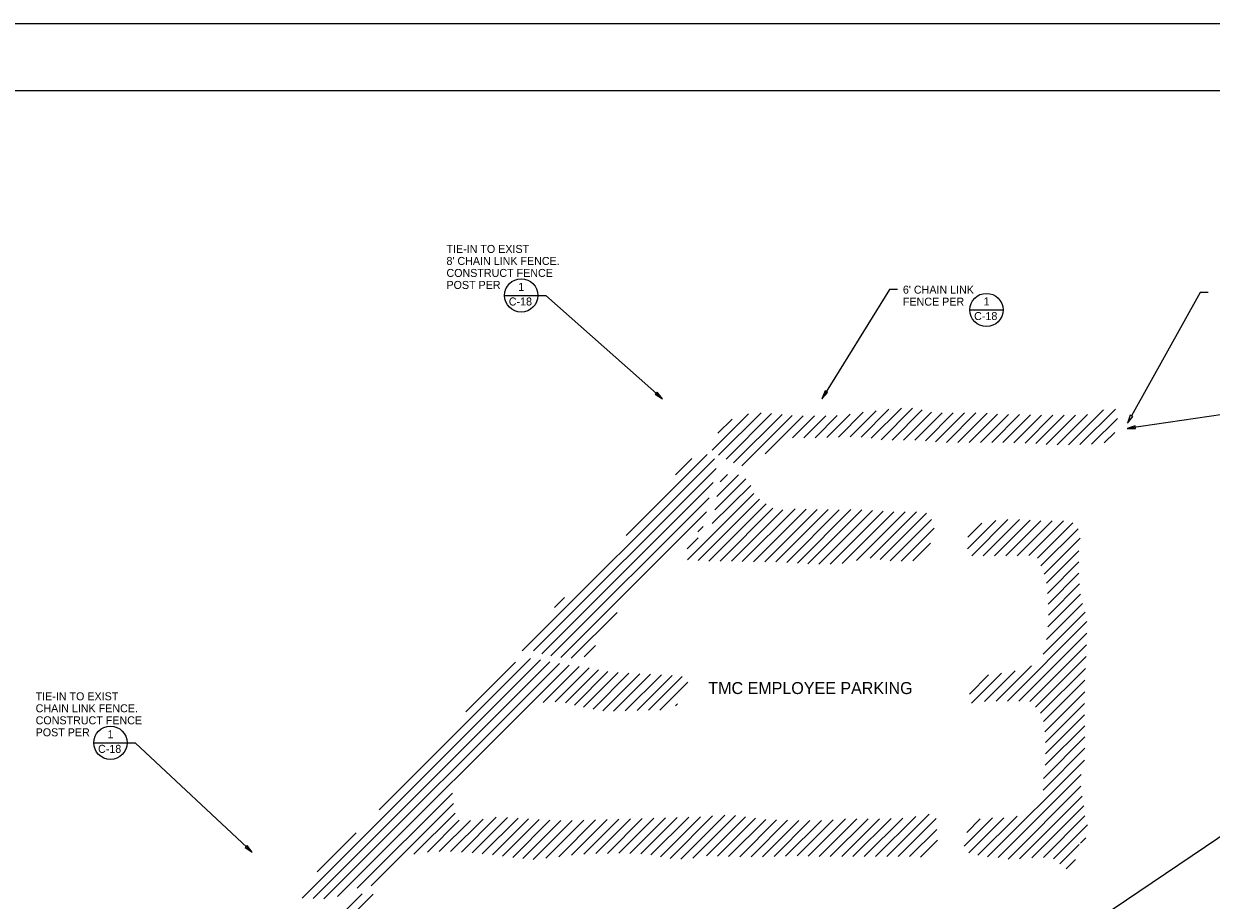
# Model space of a CAD drawing. Extents: x 0 to 3.5, y 0 to 2.5.
# Drawn here: x 0.765 to 2.248, y 1.404 to 2.5 of the extents above; entities that cross this region are included whole.
import ezdxf

# ---------------------------------------------------------------- set-up
doc = ezdxf.new("R2010")
doc.units = 0
for name, color, linetype in [('C-MARK', 7, 'Continuous'), ('C-TEXT', 7, 'Continuous'), ('C-TEXT-TITL', 7, 'Continuous'), ('G-TTLB-OTLN', 7, 'Continuous'), ('G-TTLB-VIEW', 7, 'Continuous'), ('Pavement Hatch', 7, 'Continuous')]:
    doc.layers.add(name, color=color, linetype=linetype)

msp = doc.modelspace()

# ---------------------------------------------------------------- linework, layer by layer
at = {"layer": 'C-MARK'}
for p, q in [((1.3652, 2.1604), (1.4069, 2.1604)), ((1.9466, 2.1422), (1.9882, 2.1422)), ((0.852, 1.6012), (0.8936, 1.6012))]:
    msp.add_line(p, q, dxfattribs=at)
for points in [[(1.8564, 2.1678), (1.8464, 2.1678), (1.7619, 2.0313)], [(1.4069, 2.1604), (1.4169, 2.1604), (1.5626, 2.0313)], [(2.2446, 2.164), (2.2346, 2.164), (2.1487, 2.01)], [(2.29, 2.0142), (2.28, 2.0142), (2.1431, 1.9941)], [(0.8936, 1.6012), (0.9036, 1.6012), (1.0499, 1.4646)], [(2.3985, 1.5709), (2.3885, 1.5709), (2.1092, 1.3821)]]:
    msp.add_lwpolyline(points, dxfattribs=at)
for centre in [(1.3861, 2.1604), (1.9674, 2.1422), (0.8728, 1.6012)]:
    msp.add_circle(centre, 0.0208, dxfattribs=at)
at = {"layer": 'C-TEXT'}
for points in [[(1.5536, 2.0368), (1.5626, 2.0313), (1.556, 2.0395)], [(1.7658, 2.0411), (1.7619, 2.0313), (1.7689, 2.0392)], [(2.1471, 2.0109), (2.1436, 2.0009), (2.1503, 2.0091)], [(2.1531, 1.9975), (2.1431, 1.9941), (2.1536, 1.9939)], [(1.041, 1.4703), (1.0499, 1.4646), (1.0435, 1.473)]]:
    msp.add_lwpolyline(points, close=True, dxfattribs=at)
at = {"layer": 'G-TTLB-OTLN'}
msp.add_lwpolyline([(0, 0), (3.5, 0), (3.5, 2.5), (0, 2.5)], close=True, dxfattribs=at)
at = {"layer": 'G-TTLB-VIEW'}
msp.add_lwpolyline([(0.1667, 2.4167), (3.0729, 2.4167), (3.0729, 0.0833), (0.1667, 0.0833)], close=True, dxfattribs=at)
at = {"layer": 'Pavement Hatch'}
for p, q in [((1.8108, 1.9833), (1.8456, 2.0181)), ((1.8234, 1.9818), (1.8612, 2.0195)), ((1.8357, 1.9799), (1.8751, 2.0193)), ((2.0842, 1.9739), (2.1286, 2.0182)), ((1.6247, 1.9668), (1.6702, 2.0124)), ((1.6317, 1.9881), (1.6495, 2.0058)), ((1.6326, 1.9607), (1.6857, 2.0138)), ((1.642, 1.9559), (1.6987, 2.0126)), ((1.6513, 1.9511), (1.712, 2.0117)), ((1.6617, 1.9473), (1.7248, 2.0105)), ((1.691, 1.9625), (1.7384, 2.0098)), ((1.7249, 1.9822), (1.7525, 2.0098)), ((1.7391, 1.9823), (1.7665, 2.0097)), ((1.7533, 1.9824), (1.781, 2.0101)), ((1.768, 1.9829), (1.7971, 2.012)), ((1.7826, 1.9834), (1.8135, 2.0143)), ((1.7969, 1.9835), (1.8296, 2.0163)), ((1.8495, 1.9795), (1.8871, 2.0172)), ((1.8636, 1.9795), (1.8987, 2.0146)), ((1.8777, 1.9795), (1.9119, 2.0136)), ((1.8911, 1.9788), (1.926, 2.0136)), ((1.9037, 1.9772), (1.9401, 2.0136)), ((1.9173, 1.9767), (1.9543, 2.0136)), ((1.9315, 1.9767), (1.9682, 2.0134)), ((1.9456, 1.9767), (1.981, 2.012)), ((1.9598, 1.9767), (1.9948, 2.0117)), ((1.9739, 1.9767), (2.0086, 2.0114)), ((1.9879, 1.9765), (2.0224, 2.011)), ((2.0018, 1.9763), (2.0363, 2.0108)), ((2.0156, 1.9759), (2.0504, 2.0108)), ((2.0291, 1.9753), (2.0646, 2.0108)), ((2.0419, 1.974), (2.0787, 2.0108)), ((2.0559, 1.9738), (2.0936, 2.0115)), ((2.07, 1.9738), (2.1136, 2.0174)), ((2.0988, 1.9743), (2.1312, 2.0067)), ((2.1146, 1.976), (2.1277, 1.989)), ((1.5173, 1.8603), (1.6185, 1.9615)), ((1.691, 1.9625), (1.691, 1.9625)), ((1.3873, 1.7161), (1.6274, 1.9562)), ((1.4014, 1.7161), (1.6295, 1.9442)), ((1.579, 1.9361), (1.5993, 1.9564)), ((1.6279, 1.8923), (1.6669, 1.9313)), ((1.6304, 1.9089), (1.6574, 1.936)), ((1.6346, 1.9273), (1.6438, 1.9365)), ((1.4119, 1.7124), (1.6259, 1.9264)), ((1.6248, 1.8751), (1.6728, 1.923)), ((1.4233, 1.7097), (1.621, 1.9074)), ((1.5937, 1.8298), (1.6767, 1.9128)), ((1.6071, 1.8291), (1.6837, 1.9057)), ((1.6205, 1.8284), (1.6921, 1.8999)), ((1.4354, 1.7076), (1.6175, 1.8897)), ((1.6347, 1.8284), (1.7006, 1.8943)), ((1.6487, 1.8283), (1.7129, 1.8925)), ((1.6623, 1.8278), (1.7283, 1.8937)), ((1.6762, 1.8274), (1.7421, 1.8934)), ((1.6903, 1.8275), (1.7559, 1.893)), ((1.7044, 1.8274), (1.7697, 1.8927)), ((1.7179, 1.8267), (1.7835, 1.8924)), ((1.7311, 1.8258), (1.798, 1.8928)), ((1.7444, 1.825), (1.8117, 1.8923)), ((1.7579, 1.8244), (1.825, 1.8915)), ((1.772, 1.8243), (1.8384, 1.8906)), ((1.787, 1.8252), (1.8518, 1.89)), ((1.8052, 1.8292), (1.8659, 1.8899)), ((1.822, 1.8318), (1.8801, 1.89)), ((1.8347, 1.8304), (1.8925, 1.8883)), ((1.6068, 1.8649), (1.6133, 1.8714)), ((1.847, 1.8285), (1.8989, 1.8805)), ((1.9435, 1.8435), (1.9789, 1.8789)), ((1.9443, 1.8584), (1.9616, 1.8757)), ((1.9492, 1.835), (1.9943, 1.8801)), ((1.9633, 1.835), (2.0087, 1.8804)), ((1.9775, 1.835), (2.022, 1.8795)), ((1.9916, 1.835), (2.0353, 1.8787)), ((2.0058, 1.835), (2.0494, 1.8786)), ((2.0202, 1.8353), (2.0635, 1.8786)), ((2.031, 1.832), (2.0753, 1.8763)), ((1.5933, 1.8436), (1.607, 1.8573)), ((1.861, 1.8284), (1.9019, 1.8694)), ((2.0355, 1.8223), (2.0818, 1.8687)), ((2.0395, 1.8121), (2.0843, 1.857)), ((1.8755, 1.8288), (1.8973, 1.8506)), ((2.0423, 1.8008), (2.0828, 1.8413)), ((2.0436, 1.788), (2.0828, 1.8272)), ((2.0444, 1.7746), (2.083, 1.8133)), ((2.0448, 1.7609), (2.0835, 1.7997)), ((1.4275, 1.7705), (1.4401, 1.783)), ((2.0441, 1.7461), (2.0848, 1.7868)), ((2.0425, 1.7303), (2.0873, 1.7752)), ((1.4487, 1.7068), (1.506, 1.7641)), ((1.9935, 1.6531), (2.093, 1.7526)), ((2.0383, 1.712), (2.0907, 1.7644)), ((2.0077, 1.6531), (2.093, 1.7384)), ((1.4646, 1.7085), (1.4791, 1.723)), ((2.0217, 1.653), (2.0925, 1.7237)), ((1.2088, 1.5175), (1.3977, 1.7065)), ((2.0288, 1.6459), (2.0919, 1.709)), ((1.1125, 1.4071), (1.4101, 1.7047)), ((1.1261, 1.4065), (1.422, 1.7025)), ((1.1396, 1.406), (1.4339, 1.7002)), ((1.1567, 1.4089), (1.446, 1.6982)), ((1.3169, 1.6398), (1.379, 1.7019)), ((1.4134, 1.6515), (1.4584, 1.6965)), ((1.4284, 1.6523), (1.4708, 1.6947)), ((1.4414, 1.6512), (1.4825, 1.6923)), ((1.9794, 1.6531), (2.0235, 1.6972)), ((2.0351, 1.6381), (2.0912, 1.6942)), ((1.4526, 1.6483), (1.4945, 1.6901)), ((1.4641, 1.6456), (1.5074, 1.6889)), ((1.4758, 1.6431), (1.5207, 1.6881)), ((1.4881, 1.6413), (1.5342, 1.6874)), ((1.5015, 1.6406), (1.5478, 1.6868)), ((1.5161, 1.641), (1.5614, 1.6863)), ((1.5309, 1.6416), (1.5748, 1.6855)), ((1.5451, 1.6418), (1.5873, 1.684)), ((1.5593, 1.6418), (1.5943, 1.6768)), ((1.946, 1.6621), (1.9701, 1.6862)), ((1.9487, 1.6506), (1.9862, 1.6882)), ((1.9649, 1.6528), (2.0033, 1.6911)), ((2.0388, 1.6276), (2.0905, 1.6794)), ((2.0403, 1.615), (2.0901, 1.6648)), ((1.5788, 1.6472), (1.5814, 1.6498)), ((2.0411, 1.6016), (2.0899, 1.6504)), ((2.0411, 1.5875), (2.0899, 1.6363)), ((2.0408, 1.5731), (2.0903, 1.6225)), ((2.0385, 1.5567), (2.0904, 1.6085)), ((2.0381, 1.5421), (2.0904, 1.5943)), ((1.9687, 1.4586), (2.0897, 1.5796)), ((1.9822, 1.4579), (2.0859, 1.5616)), ((1.9944, 1.4559), (2.0854, 1.547)), ((1.1812, 1.4193), (1.3003, 1.5384)), ((2.0086, 1.456), (2.087, 1.5344)), ((1.1985, 1.4224), (1.3014, 1.5253)), ((2.0242, 1.4574), (2.0889, 1.5222)), ((1.252, 1.4618), (1.3034, 1.5132)), ((1.269, 1.4646), (1.3087, 1.5043)), ((1.2837, 1.4652), (1.3226, 1.5041)), ((1.2978, 1.4651), (1.3385, 1.5058)), ((1.3113, 1.4645), (1.3549, 1.5081)), ((1.3247, 1.4637), (1.3688, 1.5078)), ((1.3375, 1.4624), (1.3821, 1.507)), ((1.3502, 1.461), (1.3953, 1.506)), ((1.3629, 1.4595), (1.4084, 1.5051)), ((1.3755, 1.458), (1.4218, 1.5043)), ((1.3882, 1.4566), (1.4357, 1.504)), ((1.4012, 1.4554), (1.4499, 1.5041)), ((1.4167, 1.4568), (1.4643, 1.5043)), ((1.4329, 1.4588), (1.4789, 1.5048)), ((1.4489, 1.4607), (1.4935, 1.5053)), ((1.4642, 1.4619), (1.5082, 1.5058)), ((1.4792, 1.4627), (1.5228, 1.5063)), ((1.4937, 1.463), (1.5372, 1.5066)), ((1.5079, 1.4631), (1.5517, 1.5069)), ((1.5218, 1.4629), (1.5662, 1.5073)), ((1.5356, 1.4625), (1.5808, 1.5077)), ((1.5482, 1.461), (1.5955, 1.5082)), ((1.5601, 1.4588), (1.6102, 1.5088)), ((1.5722, 1.4567), (1.6253, 1.5098)), ((1.5855, 1.4559), (1.6406, 1.5109)), ((1.6007, 1.4569), (1.6539, 1.5101)), ((1.6177, 1.4597), (1.6665, 1.5086)), ((1.6314, 1.4594), (1.679, 1.5069)), ((1.6452, 1.459), (1.6917, 1.5055)), ((1.6592, 1.4588), (1.7051, 1.5048)), ((1.6733, 1.4588), (1.7188, 1.5043)), ((1.6875, 1.4588), (1.7328, 1.5041)), ((1.702, 1.4592), (1.7468, 1.5041)), ((1.7165, 1.4596), (1.7612, 1.5042)), ((1.7307, 1.4597), (1.776, 1.505)), ((1.7446, 1.4594), (1.7914, 1.5062)), ((1.7585, 1.4591), (1.8056, 1.5063)), ((1.7723, 1.4589), (1.8197, 1.5063)), ((1.7865, 1.4589), (1.8339, 1.5063)), ((1.8006, 1.4589), (1.8484, 1.5066)), ((1.8148, 1.4589), (1.863, 1.5071)), ((1.8289, 1.4589), (1.8791, 1.5091)), ((1.8431, 1.4589), (1.896, 1.5118)), ((1.8572, 1.4589), (1.9047, 1.5064)), ((1.9396, 1.4719), (1.9749, 1.5072)), ((1.9427, 1.4891), (1.9596, 1.506)), ((1.9455, 1.4636), (1.9891, 1.5072)), ((1.9567, 1.4606), (2.0056, 1.5095)), ((2.0388, 1.458), (2.0905, 1.5097)), ((2.0513, 1.4563), (2.0937, 1.4987)), ((1.1311, 1.4398), (1.18, 1.4888)), ((1.8713, 1.4589), (1.9052, 1.4927)), ((1.8849, 1.4583), (1.9063, 1.4796)), ((2.0592, 1.45), (2.0832, 1.474)), ((2.0849, 1.4758), (2.0915, 1.4824)), ((2.067, 1.4437), (2.0786, 1.4553)), ((1.1241, 1.3489), (1.1875, 1.4123)), ((1.1383, 1.3489), (1.2012, 1.4119))]:
    msp.add_line(p, q, dxfattribs=at)

# ---------------------------------------------------------------- texts
at = {"layer": 'C-TEXT'}
for s, p in [('TIE-IN TO EXIST', (1.2927, 2.2135)), ("8' CHAIN LINK FENCE.", (1.2927, 2.1985)), ('CONSTRUCT FENCE ', (1.2927, 2.1835)), ('POST PER', (1.2927, 2.1685)), ('1', (1.3825, 2.1661)), ("6' CHAIN LINK", (1.863, 2.1626)), ('C-18', (1.3706, 2.1478)), ('FENCE PER', (1.863, 2.1476)), ('1', (1.9638, 2.1479)), ('C-18', (1.952, 2.1296)), ('TIE-IN TO EXIST', (0.7794, 1.6543)), ('CHAIN LINK FENCE.', (0.7794, 1.6393)), ('CONSTRUCT FENCE ', (0.7794, 1.6243)), ('POST PER', (0.7794, 1.6093)), ('1', (0.8692, 1.6069)), ('C-18', (0.8574, 1.5886))]:
    msp.add_text(s, height=0.01, dxfattribs=at).set_placement(p)
at = {"layer": 'C-TEXT-TITL'}
msp.add_text('TMC EMPLOYEE PARKING', height=0.015, dxfattribs=at).set_placement((1.6199, 1.6621))

doc.saveas('drawing.dxf')
